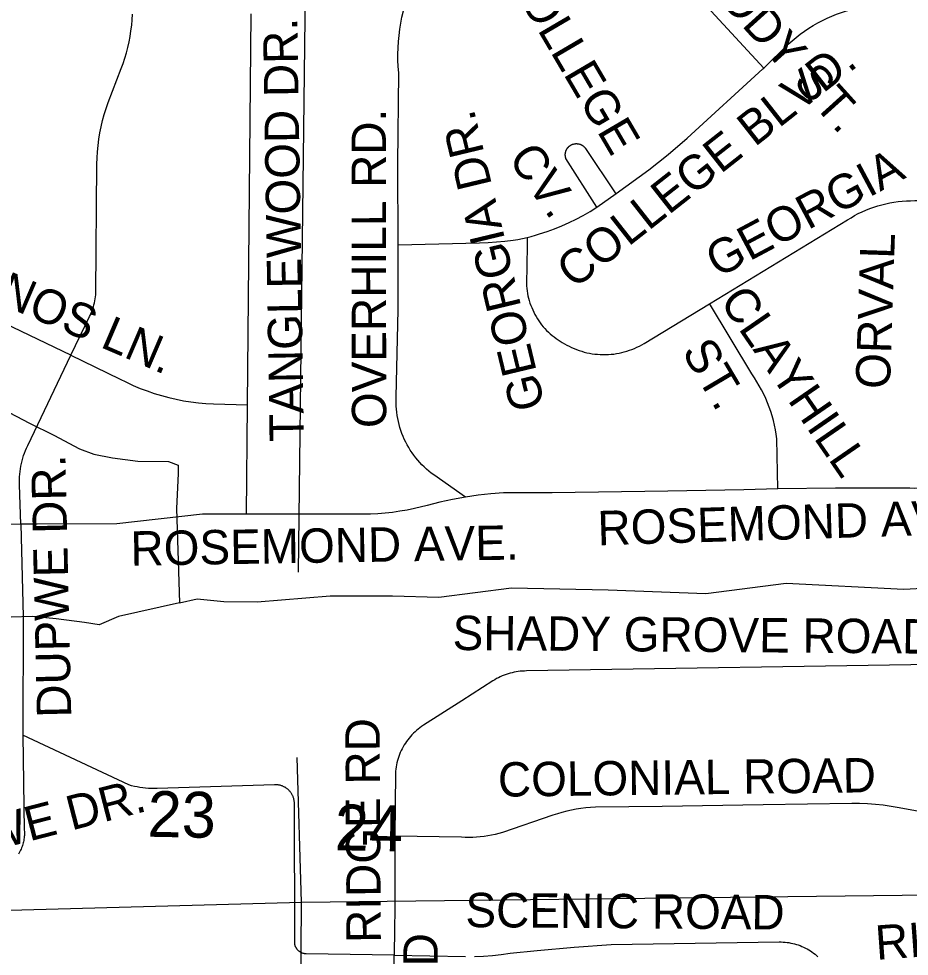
# Model space of a CAD drawing. Extents: x 1670563 to 1761545, y 515755 to 578944.
# Drawn here: x 1687869 to 1689813, y 543926 to 545971 of the extents above; entities that cross this region are included whole.
import ezdxf

# ---------------------------------------------------------------- set-up
doc = ezdxf.new("R2010")
doc.units = 0
for name, color, linetype in [('5_sectionlines', 7, 'Continuous'), ('62_text', 7, 'Continuous'), ('SHP_LINE', 7, 'Continuous'), ('STREETCL', 7, 'Continuous'), ('STRNAMES', 7, 'Continuous')]:
    doc.layers.add(name, color=color, linetype=linetype)

msp = doc.modelspace()

# ---------------------------------------------------------------- linework, layer by layer
at = {"layer": '5_sectionlines'}
for points in [[(1688479.9, 544764.2), (1688534.5, 549296.2), (1688506.7, 550235.5)], [(1688473.4, 542144.3), (1688486.3, 544044.1), (1688476.9, 544359.8)], [(1685823.9, 543970.2), (1688486.3, 544044.1), (1693687.1, 544103.2), (1698961.5, 544118.1), (1704285.9, 544155), (1709574.3, 544171.9), (1714958.5, 544246.7), (1716656.1, 544265.6)]]:
    msp.add_lwpolyline(points, dxfattribs=at)
at = {"layer": 'SHP_LINE'}
for points in [[(1685799, 545725), (1686176, 545616), (1686470, 545525), (1686865, 545460), (1687137, 545361), (1687242, 545345), (1687353, 545348), (1687446, 545321), (1687516, 545297), (1687586, 545250), (1687684, 545193), (1687749, 545161), (1687805, 545135), (1687893, 545089), (1687946, 545063), (1688002, 545033), (1688033, 545021), (1688074, 545013), (1688129, 545006), (1688196, 545005), (1688217, 544997), (1688217, 544979), (1688214, 544903), (1688220, 544697)], [(1688220, 544697), (1688259, 544706), (1688317, 544700), (1688390, 544699), (1688549, 544712), (1688685, 544712), (1688786, 544709), (1688945, 544730), (1689156, 544725), (1689369, 544717), (1689544, 544740), (1689801, 544727), (1690045, 544740), (1690103, 544736), (1690153, 544729), (1690173, 544729), (1690186, 544735), (1690209, 544742), (1690223, 544741), (1690243, 544738), (1690263, 544732), (1690343, 544730)], [(1688220, 544697), (1688087, 544667), (1688045, 544649), (1688013, 544654), (1687951, 544662), (1687899, 544667), (1687853, 544666), (1687703, 544663)]]:
    msp.add_lwpolyline(points, dxfattribs=at)
at = {"layer": 'STREETCL'}
for points in [[(1689256.5, 546122.2), (1689495.4, 545863.7)], [(1689495.4, 545863.7), (1689548.6, 545915.8), (1689557.1, 545923.3), (1689565.8, 545930.6), (1689574.8, 545937.5), (1689584.1, 545944.1), (1689593.5, 545950.4), (1689603.2, 545956.4), (1689613, 545962.1), (1689623.1, 545967.3), (1689633.3, 545972.3), (1689643.7, 545976.9), (1689654.3, 545981.1), (1689664.9, 545985), (1689675.8, 545988.5), (1689686.7, 545991.6), (1689697.7, 545994.3), (1689708.8, 545996.7), (1689720, 545998.6), (1689731.3, 546000.2), (1689742.6, 546001.4), (1689753.9, 546002.2), (1689765.3, 546002.6)], [(1687982.8, 545237.4), (1688024.1, 545321.5), (1688026, 545325.6), (1688027.7, 545329.7), (1688029.4, 545333.9), (1688030.9, 545338.1), (1688032.3, 545342.4), (1688033.5, 545346.8), (1688034.5, 545351.1), (1688035.5, 545355.5), (1688036.3, 545360), (1688036.9, 545364.4), (1688037.4, 545368.9), (1688037.7, 545373.4), (1688040.1, 545653.7), (1688040.5, 545667.5), (1688041.3, 545681.2), (1688042.6, 545694.9), (1688044.3, 545708.6), (1688046.5, 545722.1), (1688049.2, 545735.6), (1688052.3, 545749), (1688055.9, 545762.3), (1688060, 545775.4), (1688064.4, 545788.5), (1688093.1, 545862.3), (1688097.4, 545873.8), (1688101.2, 545885.3), (1688104.6, 545897), (1688107.7, 545908.8), (1688110.3, 545920.7), (1688112.6, 545932.6), (1688114.4, 545944.7), (1688115.9, 545956.8), (1688116.9, 545968.9), (1688117.5, 545981)], [(1688368.7, 545128.9), (1688376.4, 545982.1)], [(1688697.2, 545478.1), (1688696.6, 545655.3), (1688698.7, 545853.5), (1688697.6, 545867.1), (1688697, 545880.6), (1688696.9, 545894.2), (1688697.2, 545907.7), (1688698, 545921.2), (1688699.3, 545934.7), (1688701, 545948.2), (1688703.1, 545961.6), (1688705.7, 545974.9), (1688708.8, 545988.1)], [(1689173.1, 545590.2), (1689244.3, 545641.3), (1689286.6, 545675.3), (1689327.9, 545710.6), (1689493.4, 545861.7), (1689495.4, 545863.7)], [(1689131, 545560), (1689063.6, 545666.3), (1689063.4, 545667.1), (1689063.1, 545667.9), (1689062.9, 545668.7), (1689062.7, 545669.5), (1689062.6, 545670.3), (1689062.4, 545671.1), (1689062.3, 545672), (1689062.2, 545672.8), (1689062.2, 545673.7), (1689062.2, 545674.5), (1689062.2, 545675.3), (1689062.2, 545676.2), (1689062.3, 545677), (1689062.4, 545677.8), (1689062.5, 545678.7), (1689062.7, 545679.5), (1689062.9, 545680.3), (1689063.1, 545681.1), (1689063.3, 545681.9), (1689063.6, 545682.7), (1689063.9, 545683.5), (1689064.2, 545684.3), (1689064.6, 545685.1), (1689065, 545685.8), (1689065.4, 545686.5), (1689065.8, 545687.3), (1689066.3, 545688), (1689066.7, 545688.7), (1689067.2, 545689.3), (1689067.8, 545690), (1689068.3, 545690.6), (1689068.9, 545691.2), (1689069.5, 545691.8), (1689070.1, 545692.4), (1689070.7, 545693), (1689071.4, 545693.5), (1689072, 545694), (1689072.7, 545694.5), (1689073.4, 545694.9), (1689074.2, 545695.4), (1689074.9, 545695.8), (1689075.6, 545696.2), (1689076.4, 545696.5), (1689077.2, 545696.9), (1689077.9, 545697.2), (1689078.7, 545697.5), (1689079.5, 545697.7), (1689080.4, 545697.9), (1689081.2, 545698.1), (1689082, 545698.3), (1689082.8, 545698.4), (1689083.7, 545698.5), (1689084.5, 545698.6), (1689085.3, 545698.7), (1689086.2, 545698.7), (1689087, 545698.7), (1689087.9, 545698.6), (1689088.7, 545698.6), (1689089.5, 545698.5), (1689090.4, 545698.3), (1689091.2, 545698.2), (1689092, 545698), (1689092.8, 545697.8), (1689093.6, 545697.6), (1689094.4, 545697.3), (1689095.2, 545697), (1689096, 545696.7), (1689096.7, 545696.3), (1689097.5, 545695.9), (1689098.2, 545695.5), (1689099, 545695.1), (1689099.7, 545694.7), (1689100.4, 545694.2), (1689101, 545693.7), (1689101.7, 545693.2), (1689102.3, 545692.6), (1689102.9, 545692.1), (1689103.5, 545691.5), (1689104.1, 545690.9), (1689104.7, 545690.2), (1689105.2, 545689.6), (1689105.7, 545688.9), (1689106.2, 545688.2), (1689172.1, 545589.5)], [(1689131, 545560), (1689173.1, 545590.2)], [(1689377, 545349.6), (1689677.9, 545532.4), (1689685.7, 545537.2), (1689693.6, 545541.7), (1689701.6, 545546), (1689709.8, 545550), (1689718.2, 545553.6), (1689726.6, 545557), (1689735.2, 545560.2), (1689743.9, 545563), (1689752.7, 545565.5), (1689761.5, 545567.7), (1689770.4, 545569.6), (1689779.4, 545571.1), (1689788.5, 545572.4), (1689797.5, 545573.4), (1689806.6, 545574), (1689815.7, 545574.3), (1689824.9, 545574.4), (1689842.9, 545574.6)], [(1688978.8, 545494), (1688988, 545496.3), (1688997.1, 545498.8), (1689006.2, 545501.6), (1689022.6, 545507), (1689038.9, 545512.9), (1689054.9, 545519.4), (1689070.7, 545526.4), (1689086.2, 545534), (1689101.4, 545542.1), (1689116.4, 545550.8), (1689131, 545560)], [(1688697.2, 545478.1), (1688875.3, 545482.3), (1688893.6, 545483), (1688911.8, 545484.2), (1688930, 545486), (1688948.1, 545488.4), (1688958.4, 545489.9), (1688968.6, 545491.8), (1688978.8, 545494)], [(1688978.8, 545494), (1688977.9, 545415.2), (1688977.5, 545409.8), (1688977.2, 545404.4), (1688977.2, 545399), (1688977.3, 545393.6), (1688977.6, 545388.2), (1688978.1, 545382.8), (1688978.8, 545377.4), (1688979.7, 545372), (1688980.7, 545366.7), (1688982, 545361.4), (1688983.4, 545356.2), (1688985, 545351), (1688986.8, 545345.9), (1688988.8, 545340.9), (1688991, 545335.9), (1688993.3, 545331), (1688995.8, 545326.1), (1688998.4, 545321.4), (1689001.2, 545316.8), (1689004.2, 545312.3), (1689007.3, 545307.8), (1689010.6, 545303.5), (1689014.1, 545299.3), (1689017.7, 545295.2), (1689021.4, 545291.3), (1689025.2, 545287.5), (1689029.2, 545283.8), (1689033.3, 545280.3), (1689037.6, 545276.9), (1689041.9, 545273.6), (1689046.4, 545270.6), (1689050.9, 545267.6), (1689055.6, 545264.9), (1689060.4, 545262.3), (1689065.5, 545259.3), (1689070.7, 545256.6), (1689076, 545254), (1689081.4, 545251.7), (1689086.8, 545249.5), (1689092.4, 545247.5), (1689098, 545245.7), (1689103.6, 545244.1), (1689109.4, 545242.7), (1689115.1, 545241.5), (1689120.9, 545240.5), (1689126.8, 545239.7), (1689132.6, 545239.1), (1689138.5, 545238.7), (1689144.4, 545238.5), (1689150.3, 545238.5), (1689156.1, 545238.8), (1689162, 545239.2), (1689167.9, 545239.8), (1689173.7, 545240.7), (1689179.5, 545241.7), (1689185.2, 545243), (1689191, 545244.4), (1689196.6, 545246), (1689202.2, 545247.9), (1689207.7, 545249.9), (1689213.2, 545252.1), (1689218.6, 545254.5), (1689223.8, 545257.1), (1689229, 545259.9), (1689234.1, 545262.9), (1689377, 545349.6)], [(1688844.3, 544927.6), (1688775, 544976.1), (1688769.6, 544980.2), (1688764.3, 544984.4), (1688759.1, 544988.8), (1688754.1, 544993.4), (1688749.3, 544998.2), (1688744.6, 545003.2), (1688740.1, 545008.3), (1688735.8, 545013.5), (1688731.6, 545018.9), (1688727.7, 545024.4), (1688723.9, 545030.1), (1688720.4, 545035.9), (1688717, 545041.8), (1688713.9, 545047.8), (1688710.9, 545054), (1688708.2, 545060.2), (1688705.7, 545066.5), (1688703.4, 545072.9), (1688701.3, 545079.4), (1688699.5, 545086), (1688697.9, 545092.6), (1688696.5, 545099.2), (1688695.4, 545105.9), (1688694.5, 545112.7), (1688693.8, 545119.4), (1688693.3, 545126.2), (1688693.1, 545133), (1688693.1, 545139.8), (1688693.4, 545146.6), (1688697.7, 545335.8), (1688697.2, 545478.1)], [(1689526, 544945.5), (1689523.7, 545054.5), (1689522.4, 545064.6), (1689520.7, 545074.7), (1689518.6, 545084.8), (1689516.3, 545094.7), (1689513.6, 545104.6), (1689510.5, 545114.4), (1689507.2, 545124), (1689503.5, 545133.6), (1689499.5, 545143), (1689495.1, 545152.3), (1689490.5, 545161.4), (1689485.5, 545170.4), (1689480.3, 545179.2), (1689474.8, 545187.8), (1689468.9, 545196.2), (1689376.7, 545350.1)], [(1687982.8, 545237.4), (1687802.1, 545324)], [(1687874.3, 544868.4), (1687871.1, 544954.2), (1687870.9, 544960.1), (1687870.9, 544966), (1687871.1, 544971.9), (1687871.6, 544977.8), (1687872.2, 544983.7), (1687873, 544989.5), (1687874, 544995.3), (1687875.2, 545001.1), (1687876.7, 545006.8), (1687878.3, 545012.5), (1687880.1, 545018.1), (1687882.1, 545023.7), (1687884.2, 545029.2), (1687886.6, 545034.6), (1687889.1, 545039.9), (1687982.8, 545237.4)], [(1687982.8, 545237.4), (1688089.6, 545185.4), (1688104.3, 545178.1), (1688119.3, 545171.2), (1688134.4, 545164.9), (1688149.8, 545159.1), (1688165.3, 545153.8), (1688181, 545149.1), (1688196.9, 545144.9), (1688212.9, 545141.2), (1688229, 545138), (1688245.2, 545135.4), (1688261.5, 545133.4), (1688277.8, 545131.9), (1688294.2, 545130.9), (1688368.7, 545128.9)], [(1688366.6, 544890.3), (1688368.7, 545128.9)], [(1689990.6, 545000.1), (1689982.8, 544995.2), (1689974.9, 544990.4), (1689966.9, 544986), (1689958.7, 544981.7), (1689949.8, 544977.1), (1689940.7, 544972.7), (1689931.5, 544968.7), (1689922.2, 544965), (1689912.7, 544961.6), (1689903.1, 544958.6), (1689893.5, 544955.9), (1689883.7, 544953.5), (1689873.8, 544951.5), (1689863.9, 544949.9), (1689854, 544948.6), (1689844, 544947.6), (1689833.9, 544947), (1689823.9, 544946.7), (1689813.8, 544946.8), (1689651.8, 544947.3), (1689526, 544945.5)], [(1689526, 544945.5), (1689451.9, 544943.6), (1689286.1, 544940.8), (1689033.8, 544937.2), (1688927.3, 544936.7), (1688899.5, 544934.5), (1688871.8, 544931.5), (1688844.3, 544927.6)], [(1688844.3, 544927.6), (1688816.2, 544922.7), (1688788.3, 544916.9), (1688760.7, 544909.4), (1688732.9, 544902.8), (1688717.1, 544899.5), (1688701.2, 544896.7), (1688685.2, 544894.4), (1688669.2, 544892.7), (1688653.1, 544891.4), (1688637, 544890.7), (1688620.9, 544890.4), (1688366.6, 544890.3)], [(1688366.6, 544890.3), (1688270.1, 544890.1), (1688083.7, 544869.2), (1687909.8, 544868.7), (1687874.3, 544868.4)], [(1687874.3, 544868.4), (1687767.9, 544867.7), (1687604.9, 544865.4), (1687562.1, 544864.9)], [(1687874.3, 544868.4), (1687878.9, 544667.5), (1687878.7, 544408.2)], [(1690055.8, 544557.8), (1689987.9, 544561.3), (1689961.8, 544562.6), (1689935.7, 544563.1), (1689909.6, 544563.1), (1688977.7, 544548.3), (1688973.1, 544548.2), (1688968.6, 544548), (1688964, 544547.6), (1688959.5, 544547.1), (1688955, 544546.4), (1688950.5, 544545.6), (1688946, 544544.6), (1688941.6, 544543.5), (1688937.2, 544542.2), (1688932.9, 544540.8), (1688928.6, 544539.2), (1688924.4, 544537.5), (1688920.2, 544535.7), (1688916.1, 544533.7), (1688912.1, 544531.6), (1688908.1, 544529.3), (1688904.2, 544526.9), (1688836.4, 544483.5)], [(1688836.4, 544483.5), (1688752.6, 544429.9), (1688748.7, 544427.3), (1688745, 544424.5), (1688741.3, 544421.7), (1688737.7, 544418.7), (1688734.2, 544415.6), (1688730.8, 544412.4), (1688727.6, 544409.1), (1688724.4, 544405.6), (1688721.4, 544402.1), (1688718.5, 544398.4), (1688715.8, 544394.6), (1688713.1, 544390.8), (1688710.6, 544386.9), (1688708.3, 544382.8), (1688706.1, 544378.7), (1688704, 544374.5), (1688702.1, 544370.3), (1688700.3, 544366), (1688698.7, 544361.6), (1688697.2, 544357.2), (1688695.9, 544352.7), (1688694.8, 544348.2), (1688693.8, 544343.6), (1688693, 544339.1), (1688692.3, 544334.4), (1688691.8, 544329.8), (1688691.4, 544325.2), (1688690.1, 544188.3), (1688690, 544028), (1688689.1, 543985.8), (1688688.4, 543928.3)], [(1687878.7, 544408.2), (1687881.5, 544200.9), (1687881.7, 544198.1), (1687881.8, 544195.3), (1687881.8, 544192.5), (1687881.7, 544189.7), (1687881.5, 544186.9), (1687881.2, 544184.1), (1687880.8, 544181.3), (1687880.4, 544178.5), (1687879.8, 544175.8), (1687879.1, 544173.1), (1687878.4, 544170.4), (1687877.5, 544167.7), (1687876.6, 544165.1), (1687875.6, 544162.4), (1687874.5, 544159.9), (1687873.3, 544157.3), (1687872, 544154.8), (1687871.2, 544153.2), (1687870.4, 544151.6), (1687869.6, 544150), (1687868.7, 544148.4)], [(1688688.4, 543928.3), (1688496.8, 543931.2), (1688495.9, 543931.2), (1688495, 543931.3), (1688494.2, 543931.4), (1688493.3, 543931.5), (1688492.4, 543931.7), (1688491.5, 543931.8), (1688490.7, 543932.1), (1688489.8, 543932.3), (1688489, 543932.6), (1688488.1, 543932.9), (1688487.3, 543933.2), (1688486.5, 543933.6), (1688485.7, 543933.9), (1688484.9, 543934.4), (1688484.1, 543934.8), (1688483.4, 543935.3), (1688482.6, 543935.8), (1688481.9, 543936.3), (1688481.2, 543936.8), (1688480.5, 543937.4), (1688479.8, 543938), (1688479.2, 543938.6), (1688478.6, 543939.2), (1688478, 543939.9), (1688477.4, 543940.6), (1688476.8, 543941.3), (1688476.3, 543942), (1688475.8, 543942.7), (1688475.3, 543943.5), (1688474.9, 543944.2), (1688474.5, 543945), (1688474.1, 543945.8), (1688473.7, 543946.6), (1688473.4, 543947.5), (1688473, 543948.3), (1688472.8, 543949.1), (1688472.5, 543950), (1688472.3, 543950.9), (1688472.1, 543951.7), (1688471.9, 543952.6), (1688471.8, 543953.5), (1688471.7, 543954.4), (1688471.6, 543955.3), (1688471.6, 543956.1), (1688471, 544259.1), (1688470.9, 544260.5), (1688470.9, 544261.9), (1688470.7, 544263.4), (1688470.6, 544264.8), (1688470.3, 544266.2), (1688470.1, 544267.6), (1688469.7, 544269), (1688469.4, 544270.3), (1688469, 544271.7), (1688468.5, 544273.1), (1688468, 544274.4), (1688467.4, 544275.7), (1688466.8, 544277), (1688466.2, 544278.3), (1688465.5, 544279.5), (1688464.8, 544280.7), (1688464, 544281.9), (1688463.2, 544283.1), (1688462.3, 544284.2), (1688461.4, 544285.4), (1688460.5, 544286.4), (1688459.5, 544287.5), (1688458.5, 544288.5), (1688457.5, 544289.5), (1688456.4, 544290.4), (1688455.3, 544291.3), (1688454.2, 544292.2), (1688453, 544293), (1688451.8, 544293.8), (1688450.6, 544294.5), (1688449.4, 544295.2), (1688448.1, 544295.9), (1688446.8, 544296.5), (1688445.5, 544297.1), (1688444.2, 544297.6), (1688442.9, 544298.1), (1688441.5, 544298.5), (1688440.1, 544298.9), (1688438.7, 544299.2), (1688437.3, 544299.5), (1688435.9, 544299.7), (1688434.5, 544299.9), (1688433.1, 544300.1), (1688431.7, 544300.2), (1688430.3, 544300.2), (1688428.8, 544300.2), (1688427.4, 544300.1), (1688171.3, 544291.7), (1688165.1, 544291.6), (1688158.9, 544291.7), (1688152.6, 544292), (1688146.4, 544292.6), (1688140.2, 544293.3), (1688134, 544294.2), (1688127.9, 544295.3), (1688121.8, 544296.6), (1688115.7, 544298.1), (1688109.7, 544299.8), (1687878.7, 544408.2)], [(1689893.9, 544230.9), (1689790.4, 544250), (1689773.4, 544252.9), (1689756.2, 544255.3), (1689739, 544257.1), (1689721.8, 544258.4), (1689704.5, 544259.2), (1689687.2, 544259.5), (1689493.7, 544256.6), (1689273.4, 544252.7), (1689127.9, 544251), (1689117.3, 544250.4), (1689106.8, 544249.5), (1689096.3, 544248.2), (1689085.9, 544246.7), (1689075.5, 544244.7), (1689065.2, 544242.5), (1689054.9, 544239.9), (1689044.8, 544236.9), (1689034.7, 544233.7), (1688925, 544196.3), (1688917.1, 544194), (1688909.1, 544191.9), (1688901, 544190.1), (1688892.9, 544188.5), (1688884.8, 544187.2), (1688876.6, 544186.3), (1688868.3, 544185.5), (1688860.1, 544185.1), (1688851.8, 544185), (1688843.6, 544185.1), (1688835.3, 544185.5), (1688690.1, 544188.3)], [(1688864.2, 543925.6), (1688883.6, 543926.3), (1688903.1, 543927.6), (1688922.5, 543929.7), (1688941.8, 543932.4), (1689001, 543938.6), (1689081.6, 543946), (1689162.4, 543951.5), (1689529.2, 543957.2), (1689533.4, 543957.2), (1689537.6, 543957), (1689541.8, 543956.7), (1689546, 543956.3), (1689550.2, 543955.7), (1689554.3, 543954.9), (1689558.4, 543954.1), (1689562.5, 543953.1), (1689566.5, 543951.9), (1689570.5, 543950.6), (1689574.5, 543949.2), (1689578.4, 543947.6), (1689582.2, 543945.9), (1689586, 543944), (1689589.7, 543942.1), (1689593.4, 543940), (1689597, 543937.8), (1689600.5, 543935.4), (1689603.9, 543932.9), (1689607.2, 543930.4), (1689610.4, 543927.7), (1689613.6, 543924.9)], [(1688686.2, 543737.7), (1688688.4, 543928.3)], [(1688688.4, 543928.3), (1688844.7, 543925.6)]]:
    msp.add_lwpolyline(points, dxfattribs=at)

# ---------------------------------------------------------------- texts
at = {"layer": '62_text'}
for s, p in [('23', (1688150, 544186.8)), ('24', (1688558.4, 544157.4))]:
    msp.add_text(s, height=100, rotation=358.9302, dxfattribs=at).set_placement(p)
at = {"layer": 'STRNAMES'}
for s, rotation, p in [('BUDDY ST.', 312.057, (1689303.6, 546113.8)), ('COLLEGE', 300.3979, (1688924.4, 546077)), ('TANGLEWOOD DR.', 90.9083, (1688491.9, 545048.8)), ('COLLEGE BLVD.', 38.2109, (1689081.5, 545380)), ('OVERHILL RD.', 90.0708, (1688671.5, 545078.3)), ('GEORGIA DR.', 103.4978, (1689018.3, 545126.1)), ('CV.', 305.1574, (1688935.7, 545666.5)), ('GEORGIA ', 28.0694, (1689395.1, 545404.9)), ('ORVAL', 88.1165, (1689770.5, 545162.7)), ('MUNOS LN.', 336.7967, (1687676.3, 545413.8)), ('CLAYHILL ', 304.5926, (1689397.4, 545355.1)), ('ST.', 300.6779, (1689315, 545245.2)), ('DUPWE DR.', 91.306, (1687984.2, 544447.3)), ('ROSEMOND AVE.', 1.7772, (1689133.6, 544822.3)), ('ROSEMOND AVE.', 0.9083, (1688113.9, 544778)), ('SHADY GROVE ROAD', 359.56, (1688816.1, 544594.1)), ('RIDGE RD', 90.3331, (1688659.7, 543955.3)), ('COLONIAL ROAD', 0.6833, (1688915.6, 544274)), ('DUPWE DR.', 14.4748, (1687596.1, 544099.9)), ('SCENIC ROAD', 359.56, (1688844, 543989.6)), ('RICH RD', 4.1391, (1689741.3, 543918)), ('RIDGE   RD', 90.0254, (1688784, 543430.5))]:
    msp.add_text(s, height=75, rotation=rotation, dxfattribs=at).set_placement(p)

doc.saveas('drawing.dxf')
